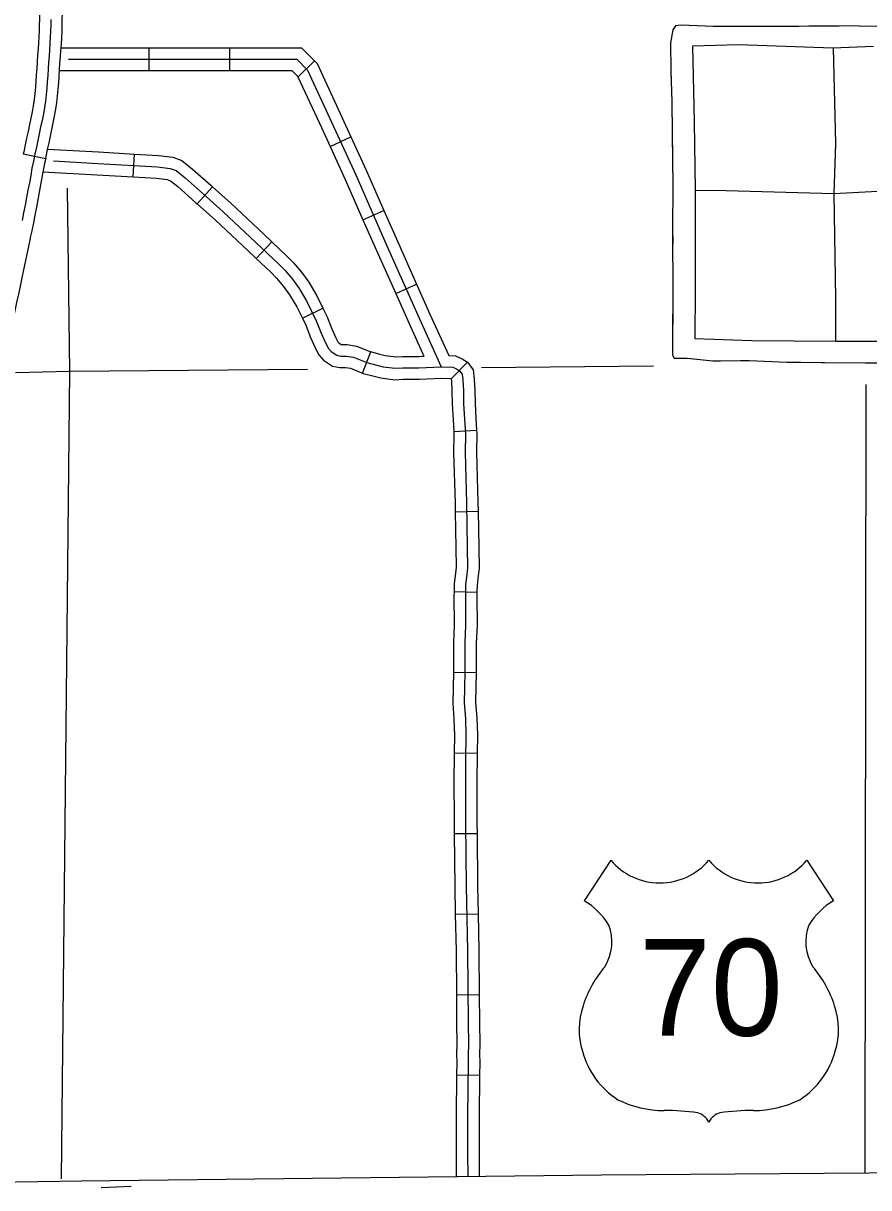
# Model space of a CAD drawing. Extents: x 1127717 to 1741049, y 2026793 to 2244711.
# Drawn here: x 1294439 to 1299981, y 2075219 to 2082851 of the extents above; entities that cross this region are included whole.
import ezdxf

# ---------------------------------------------------------------- set-up
doc = ezdxf.new("R2010")
doc.units = 0
for name, color, linetype in [('15', 7, 'Continuous'), ('22', 7, 'Continuous'), ('31', 7, 'Continuous'), ('32', 7, 'Continuous'), ('35', 7, 'Continuous'), ('43', 7, 'Continuous'), ('5', 7, 'Continuous')]:
    doc.layers.add(name, color=color, linetype=linetype)

msp = doc.modelspace()

# ---------------------------------------------------------------- linework, layer by layer
at = {"layer": '15'}
msp.add_lwpolyline([(1291960.3, 2075242.5), (1293674.3, 2075245.9), (1294820.5, 2075264.7), (1298229, 2075302), (1299981.5, 2075316.3), (1302519.4, 2075326.7), (1304059.9, 2075347.2)], dxfattribs=at)
at = {"layer": '22'}
for p, q in [((1298289.8, 2077366.3), (1298116.7, 2077098.6)), ((1299576.7, 2077366.3), (1299749.8, 2077098.6))]:
    msp.add_line(p, q, dxfattribs=at)
for centre, radius, start, end in [((1298612.1, 2077637.5), 421.2, 220.07504, 319.67012), ((1299254.4, 2077637.5), 421.2, 220.32988, 319.92496), ((1297890.6, 2076710), 449.7, 30.7809, 59.98827), ((1299976, 2076710), 449.7, 120.01173, 149.2191), ((1297989.5, 2076828.6), 308.3, 328.81046, 21.21077), ((1299877, 2076828.6), 308.3, 158.78923, 211.18954), ((1298795.6, 2076196.8), 719.2, 138.95648, 162.69135), ((1299070.9, 2076196.8), 719.2, 17.30865, 41.04352), ((1298558.2, 2076255.7), 475.2, 160.95764, 197.38186), ((1299308.3, 2076255.7), 475.2, 342.61814, 19.04236), ((1298635.6, 2076257), 549.9, 195.10743, 237.13119), ((1299230.9, 2076257), 549.9, 302.86881, 344.89257), ((1298645.8, 2076430.2), 706, 244.07708, 269.57785), ((1299220.7, 2076430.2), 706, 270.42215, 295.92292), ((1298662.1, 2074431.1), 1293.3, 81.19416, 90.95387), ((1299204.4, 2074431.1), 1293.3, 89.04613, 98.80584), ((1298823.9, 2075590.6), 123.9, 28.03422, 72.98637), ((1299042.6, 2075590.6), 123.9, 107.01363, 151.96578)]:
    msp.add_arc(centre, radius, start, end, dxfattribs=at)
at = {"layer": '31'}
msp.add_line((1294439.2, 2081996.3), (1294586, 2081965.3), dxfattribs=at)
for points in [[(1294547.2, 2083091.6), (1294545.7, 2082993.1), (1294545.6, 2082953.3), (1294545.5, 2082915.4), (1294544.7, 2082877.6), (1294544.3, 2082840), (1294543.2, 2082802), (1294541.6, 2082763), (1294539.2, 2082723.6), (1294536.2, 2082683.1), (1294533.1, 2082641.4), (1294530.1, 2082599.1), (1294527.2, 2082556.4), (1294524.7, 2082514.3), (1294524.1, 2082506.4)], [(1294673.7, 2082495.5), (1294674.4, 2082504.4), (1294676.9, 2082546.9), (1294679.7, 2082588.7), (1294682.7, 2082630.5), (1294685.8, 2082671.9), (1294688.9, 2082713.5), (1294691.4, 2082755.5), (1294693.1, 2082796.7), (1294694.3, 2082837), (1294694.7, 2082875.3), (1294695.5, 2082913.6), (1294695.6, 2082952.9), (1294695.7, 2082991.8), (1294697.1, 2083085)], [(1294619.7, 2082876.5), (1294619.3, 2082838.5), (1294618.1, 2082799.4), (1294616.5, 2082759.2), (1294614, 2082718.6), (1294611, 2082677.5), (1294607.9, 2082635.9), (1294604.9, 2082593.9), (1294602.1, 2082551.7), (1294599.6, 2082509.4), (1294596.5, 2082467.2), (1294593, 2082425.2), (1294589.1, 2082383.3), (1294584.5, 2082341.3), (1294578.5, 2082299.1), (1294571.1, 2082256.7), (1294562.1, 2082214.1), (1294552.7, 2082171.4), (1294543.7, 2082127.5), (1294534.4, 2082083.3), (1294525, 2082038.4), (1294515.2, 2081993), (1294505.5, 2081947.1), (1294496.3, 2081900.7), (1294487.6, 2081853.5), (1294479, 2081805.8), (1294469.9, 2081757.5), (1294460.8, 2081708.6), (1294451.5, 2081659), (1294441.7, 2081608.9), (1294431.6, 2081558.2)], [(1294524.1, 2082506.4), (1294521.7, 2082473), (1294518.3, 2082431.8), (1294514.5, 2082390.8), (1294510.1, 2082350.6), (1294504.4, 2082310.9), (1294497.4, 2082270.9), (1294488.8, 2082229.9), (1294479.3, 2082187), (1294470.3, 2082142.7), (1294461, 2082098.7), (1294451.7, 2082054.1), (1294441.8, 2082008.7), (1294439.2, 2081996.3)], [(1294586, 2081965.3), (1294588.5, 2081977.3), (1294598.4, 2082022.8), (1294607.8, 2082067.8), (1294617.1, 2082112.3), (1294626, 2082155.8), (1294635.4, 2082198.3), (1294644.7, 2082242.5), (1294652.6, 2082287.3), (1294659, 2082331.9), (1294663.7, 2082375.8), (1294667.7, 2082418.6), (1294671.3, 2082461.4), (1294673.7, 2082495.5)], [(1294586, 2081965.3), (1294579, 2081932.1), (1294570, 2081886.6), (1294561.4, 2081840.1), (1294552.8, 2081792.2), (1294543.7, 2081743.7), (1294534.5, 2081694.7), (1294525.1, 2081644.9), (1294515.3, 2081594.4), (1294505.1, 2081543.3), (1294494.5, 2081491.8), (1294485.2, 2081447.2)], [(1294485.2, 2081447.2), (1294483.7, 2081440.1), (1294472.7, 2081388.7), (1294461.8, 2081337.3), (1294450.8, 2081286), (1294440.2, 2081234.2), (1294429.5, 2081181.6), (1294418.5, 2081128.3), (1294407.3, 2081074.6), (1294395.8, 2081021), (1294384.2, 2080967.2), (1294375.8, 2080929.6)]]:
    msp.add_lwpolyline(points, dxfattribs=at)
at = {"layer": '32'}
for p, q in [((1295264.5, 2082540.7), (1295264.5, 2082690.7)), ((1295792.5, 2082540.7), (1295792.5, 2082690.7)), ((1296240.8, 2082499.6), (1296347.4, 2082605.1)), ((1296450.7, 2082044), (1296587, 2082106.6)), ((1295160.6, 2081844.1), (1295169.2, 2081993.9)), ((1295579.4, 2081667.4), (1295679, 2081779.6)), ((1296666, 2081563.4), (1296803.4, 2081623.6)), ((1295964.9, 2081310.4), (1296068.2, 2081419.1)), ((1296880.4, 2081080.2), (1297017.3, 2081141.5)), ((1296268.7, 2080917.3), (1296403.4, 2080983.3)), ((1296662.6, 2080558.3), (1296718.3, 2080697.5)), ((1297244.3, 2080519.9), (1297351.6, 2080629.4)), ((1297261, 2080174.7), (1297410.8, 2080183.1)), ((1297270.6, 2079649.7), (1297420.6, 2079652.5)), ((1297262.8, 2079125.7), (1297412.8, 2079122.2)), ((1297258.4, 2078597.5), (1297408.3, 2078594.7)), ((1297264.5, 2078069.4), (1297414.5, 2078067.6)), ((1297263.8, 2077539.7), (1297413.8, 2077541.3)), ((1297271.1, 2077011), (1297421.1, 2077014.1)), ((1297278.6, 2076483.9), (1297428.6, 2076485.3)), ((1297280.2, 2075957.5), (1297430.1, 2075955.9))]:
    msp.add_line(p, q, dxfattribs=at)
for points in [[(1294687.2, 2082690.7), (1295264.5, 2082690.7)], [(1295264.5, 2082690.7), (1295792.5, 2082690.7)], [(1295792.5, 2082690.7), (1296262.7, 2082690.7), (1296347.4, 2082605.1)], [(1294736.5, 2082615.7), (1296231.4, 2082615.7), (1296302.1, 2082544.2), (1296461.9, 2082199), (1296618.8, 2081857.9), (1296822.9, 2081392.2), (1297037, 2080914.1), (1297178.9, 2080600.3)], [(1296347.4, 2082605.1), (1296364.7, 2082587.7), (1296530, 2082230.5), (1296587, 2082106.6)], [(1294676.5, 2082540.7), (1295264.5, 2082540.7)], [(1295264.5, 2082540.7), (1295792.5, 2082540.7)], [(1295792.5, 2082540.7), (1296200.1, 2082540.7), (1296240.8, 2082499.6)], [(1296239.6, 2082500.8), (1296393.8, 2082167.6), (1296450.7, 2082044)], [(1296587, 2082106.6), (1296687.2, 2081888.6), (1296803.4, 2081623.6)], [(1294599.1, 2082026.3), (1294932.8, 2082007.5), (1295169.2, 2081993.9)], [(1295169.2, 2081993.9), (1295326, 2081984.9), (1295419.4, 2081973.6), (1295478.7, 2081951.4), (1295549.4, 2081895.4), (1295667.9, 2081789.4), (1295679, 2081779.6)], [(1296450.7, 2082044), (1296550.3, 2081827.2), (1296666, 2081563.4)], [(1294637.8, 2081949), (1294928.5, 2081932.6), (1295319.3, 2081910.2), (1295401.5, 2081900.2), (1295441.3, 2081885.3), (1295501.1, 2081838), (1295618.1, 2081733.4), (1295750, 2081616.3), (1295964.1, 2081414.6), (1296113.4, 2081272.7), (1296155.8, 2081230.3), (1296203, 2081173.1), (1296247.9, 2081113.3), (1296297.6, 2081028.6), (1296359.9, 2080901.6), (1296392.2, 2080819.4), (1296419.6, 2080757.2), (1296439.5, 2080719.8), (1296457, 2080699.9), (1296494.3, 2080675), (1296521.7, 2080670), (1296556.5, 2080670), (1296603.8, 2080662.6), (1296691, 2080627.7), (1296748.2, 2080612.8), (1296798, 2080600.3), (1296877.7, 2080590.3), (1296927.4, 2080592.8), (1297032, 2080592.8), (1297178.9, 2080600.3)], [(1294568.4, 2081877.8), (1294924.3, 2081857.7), (1295160.6, 2081844.1)], [(1295160.6, 2081844.1), (1295312.7, 2081835.4), (1295383.5, 2081826.8), (1295404, 2081819.2), (1295452.7, 2081780.5), (1295568.2, 2081677.4), (1295579.4, 2081667.4)], [(1295679, 2081779.6), (1295800.6, 2081671.7), (1296015.6, 2081469.1), (1296068.2, 2081419.1)], [(1295579.4, 2081667.4), (1295699.4, 2081561), (1295912.5, 2081360.1), (1295964.9, 2081310.4)], [(1296803.4, 2081623.6), (1296891.5, 2081422.6), (1297017.3, 2081141.5)], [(1296666, 2081563.4), (1296754.3, 2081361.8), (1296880.4, 2081080.2)], [(1296068.2, 2081419.1), (1296165.8, 2081326.4), (1296211.3, 2081280.8), (1296262, 2081219.5), (1296310.4, 2081154.9), (1296363.7, 2081064.2), (1296403.4, 2080983.3)], [(1295964.9, 2081310.4), (1296061.1, 2081219), (1296100.2, 2081179.8), (1296144.1, 2081126.7), (1296185.3, 2081071.7), (1296231.5, 2080993.1), (1296268.7, 2080917.3)], [(1297017.3, 2081141.5), (1297105.4, 2080944.9), (1297228, 2080673.7)], [(1296880.4, 2081080.2), (1296968.6, 2080883.3), (1297065.2, 2080669.6)], [(1296403.4, 2080983.3), (1296428.6, 2080931.9), (1296461.5, 2080848.3), (1296487.1, 2080790), (1296501.7, 2080762.7), (1296506.9, 2080756.8), (1296523, 2080746), (1296528.4, 2080745), (1296562.4, 2080745), (1296623.9, 2080735.3), (1296718.3, 2080697.5)], [(1296268.7, 2080917.3), (1296291.2, 2080871.3), (1296323, 2080790.6), (1296352.1, 2080724.4), (1296377.4, 2080677), (1296407.1, 2080643), (1296465.6, 2080604), (1296514.9, 2080595), (1296550.6, 2080595), (1296583.8, 2080589.8), (1296662.6, 2080558.3)], [(1296714.5, 2080699.1), (1296766.8, 2080685.4), (1296811.8, 2080674.2), (1296880.5, 2080665.6), (1296925.6, 2080667.8), (1297030.1, 2080667.8), (1297065.2, 2080669.6)], [(1297178.9, 2080600.3), (1297255.1, 2080597.7), (1297279.3, 2080586.5), (1297299.8, 2080573.5), (1297316.6, 2080551.1), (1297320.3, 2080513.8), (1297324, 2080443), (1297325.9, 2080359.1), (1297331.5, 2080256.6), (1297337.1, 2080157.8), (1297335.2, 2080038.5), (1297344.5, 2079706.7), (1297350.1, 2079414.1), (1297352, 2079281.6), (1297346.4, 2079238.7), (1297339, 2079173.5), (1297337.1, 2079095.2), (1297339, 2078905), (1297333.4, 2078789.5), (1297333.4, 2078597.5), (1297329.6, 2078396.2), (1297337.1, 2078293.7), (1297340.8, 2078183.7), (1297339, 2078023.4), (1297337.3, 2077914.5), (1297338.1, 2077603.7), (1297342.4, 2077195.3), (1297351, 2076772), (1297355.2, 2076301.5), (1297357.4, 2076158.3), (1297355.2, 2076096.2), (1297356, 2076039.4), (1297352.2, 2075687.2), (1297352.2, 2075444.9), (1297354.4, 2075292.4)], [(1297228, 2080673.7), (1297272.8, 2080672.1), (1297315.3, 2080652.5), (1297351.6, 2080629.4), (1297389.1, 2080579.4), (1297395.1, 2080519.5), (1297399, 2080445.8), (1297400.9, 2080362), (1297406.4, 2080260.8), (1297410.8, 2080183.1)], [(1296662.5, 2080558.3), (1296667.4, 2080556.3), (1296729.6, 2080540.1), (1296784.2, 2080526.5), (1296874.9, 2080515.1), (1296929.3, 2080517.8), (1297033.9, 2080517.8), (1297182.7, 2080525.4)], [(1297176.3, 2080525.4), (1297237.4, 2080523.3), (1297243.3, 2080520.5), (1297244.3, 2080519.9), (1297245.5, 2080508.1), (1297249.1, 2080440.2), (1297251, 2080356.2), (1297256.6, 2080252.4), (1297261, 2080174.7)], [(1297261, 2080174.7), (1297262.1, 2080156.3), (1297260.2, 2080038), (1297269.6, 2079705), (1297270.6, 2079649.7)], [(1297410.8, 2080183.1), (1297412.1, 2080159.3), (1297410.2, 2080039), (1297419.5, 2079708.5), (1297420.6, 2079652.5)], [(1297270.6, 2079649.7), (1297275.1, 2079412.8), (1297276.9, 2079285.9), (1297272, 2079247.8), (1297264.1, 2079178.6), (1297262.8, 2079125.7)], [(1297420.6, 2079652.5), (1297425.1, 2079415.3), (1297427.1, 2079277.2), (1297420.9, 2079229.6), (1297413.9, 2079168.3), (1297412.8, 2079122.2)], [(1297262.8, 2079125.7), (1297262.1, 2079095.7), (1297263.9, 2078906.5), (1297258.4, 2078791.3), (1297258.4, 2078598.2), (1297258.4, 2078597.5)], [(1297412.8, 2079122.2), (1297412.1, 2079094.6), (1297414, 2078903.6), (1297408.4, 2078787.7), (1297408.4, 2078596.8), (1297408.3, 2078594.8)], [(1297258.4, 2078597.5), (1297254.6, 2078394.2), (1297262.2, 2078289.7), (1297265.8, 2078182.9), (1297264.5, 2078069.4)], [(1297408.3, 2078594.7), (1297404.7, 2078398.2), (1297412, 2078297.7), (1297415.8, 2078184.5), (1297414.5, 2078067.6)], [(1297264.5, 2078069.4), (1297264, 2078024.4), (1297262.3, 2077915), (1297263.1, 2077603.2), (1297263.8, 2077539.7)], [(1297414.5, 2078067.6), (1297413.9, 2078022.4), (1297412.3, 2077914), (1297413.1, 2077604.2), (1297413.8, 2077541.3)], [(1297263.8, 2077539.7), (1297267.4, 2077194.1), (1297271.1, 2077011)], [(1297413.8, 2077541.3), (1297417.4, 2077196.4), (1297421.1, 2077014.1)], [(1297271.1, 2077011), (1297276, 2076770.9), (1297278.6, 2076483.9)], [(1297421.1, 2077014.1), (1297426, 2076773.1), (1297428.6, 2076485.3)], [(1297278.6, 2076483.9), (1297280.2, 2076300.6), (1297282.4, 2076159), (1297280.2, 2076097), (1297281, 2076039.2), (1297280.2, 2075957.5)], [(1297428.6, 2076485.3), (1297430.2, 2076302.4), (1297432.4, 2076157.5), (1297430.3, 2076095.5), (1297431.1, 2076039.5), (1297430.1, 2075955.9)], [(1297280.2, 2075957.5), (1297277.2, 2075687.6), (1297277.2, 2075291.6)], [(1297430.1, 2075955.9), (1297427.2, 2075686.8), (1297427.2, 2075293.2)]]:
    msp.add_lwpolyline(points, dxfattribs=at)
at = {"layer": '35'}
for points in [[(1300013, 2082699.3), (1299745.9, 2082687.9), (1299128.8, 2082710.6), (1298826, 2082701), (1298836.7, 2082204.3), (1298844.3, 2081756.8), (1298844.3, 2081104.8), (1298841.1, 2080785.9), (1299214.4, 2080771.1), (1299764.8, 2080767.4), (1300214.1, 2080767.4)], [(1299748, 2082688), (1299764.5, 2082062.5), (1299753.1, 2081733.3), (1299764.5, 2081044.7), (1299764.5, 2080767.4)], [(1302817.8, 2081781.5), (1301901.4, 2081771.2), (1301213.1, 2081759.8), (1300808.4, 2081763.6), (1300040.6, 2081748.5), (1299753.1, 2081733.3), (1299045.9, 2081752.2), (1298844.3, 2081754.8)]]:
    msp.add_lwpolyline(points, dxfattribs=at)
at = {"layer": '43'}
for points in [[(1300028.3, 2082830.9), (1299815.4, 2082833.6), (1299523.7, 2082830.9), (1299171.5, 2082830.9), (1298961.2, 2082830.9), (1298751, 2082838.8), (1298714.2, 2082833.6), (1298698.4, 2082807.3), (1298682.6, 2082723.1), (1298685.2, 2082539.1), (1298690.5, 2082336.6), (1298693.1, 2082139.4), (1298698.4, 2081784.4), (1298695.8, 2081503.1), (1298698.4, 2081064), (1298695.8, 2080832.6), (1298695.8, 2080674.8), (1298706.3, 2080656.4), (1298790.4, 2080656.4), (1298958.6, 2080638), (1299197.8, 2080640.6), (1299444.8, 2080630.1), (1299691.9, 2080627.5), (1299957.3, 2080624.8), (1300314.8, 2080624.8)], [(1298731.6, 2082836.1), (1298714.2, 2082833.6), (1298698.4, 2082807.3), (1298682.6, 2082723.1), (1298685.2, 2082539.1), (1298687.3, 2082461.1)], [(1299259.3, 2082830.9), (1299171.5, 2082830.9), (1298961.2, 2082830.9), (1298863.3, 2082834.6)], [(1299589.3, 2082831.5), (1299523.7, 2082830.9), (1299391.3, 2082830.9)], [(1299787.2, 2082833.3), (1299589.3, 2082831.5)], [(1300315.2, 2082834.2), (1300028.3, 2082830.9), (1299919.2, 2082832.3)], [(1298690.6, 2082329.1), (1298693.1, 2082139.4), (1298696.2, 2081933.2)], [(1298698.1, 2081801.2), (1298698.4, 2081784.4), (1298695.8, 2081503.1), (1298696.3, 2081405.2)], [(1298697.1, 2081273.2), (1298698.4, 2081064), (1298696.3, 2080877.2)], [(1298695.8, 2080745.2), (1298695.8, 2080674.8), (1298706.3, 2080656.4), (1298790.4, 2080656.4), (1298812.5, 2080654)], [(1298812.5, 2080654), (1298958.6, 2080638), (1299009.7, 2080638.6)], [(1299141.7, 2080640), (1299197.8, 2080640.6), (1299444.8, 2080630.1), (1299537.4, 2080629.1)], [(1299669.4, 2080627.7), (1299691.9, 2080627.5), (1299957.3, 2080624.8), (1300065.4, 2080624.8)], [(1295147.5, 2075225.6), (1294949.6, 2075218.7)]]:
    msp.add_lwpolyline(points, dxfattribs=at)
at = {"layer": '5'}
for points in [[(1294727, 2081771.1), (1294741.1, 2080568.5)], [(1298570.7, 2080603.1), (1297443.2, 2080592.9)], [(1294741.1, 2080568.5), (1294387.6, 2080560)], [(1294741.1, 2080568.5), (1294687.5, 2075276.2)], [(1296302.7, 2080582.6), (1294741.1, 2080568.5)], [(1299961.5, 2080483.3), (1299956.3, 2075316.1)]]:
    msp.add_lwpolyline(points, dxfattribs=at)

# ---------------------------------------------------------------- texts
at = {"layer": '22'}
msp.add_text('70', height=633.6, dxfattribs=at).set_placement((1298475.7, 2076215))

doc.saveas('drawing.dxf')
